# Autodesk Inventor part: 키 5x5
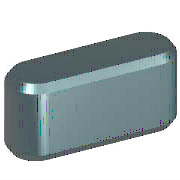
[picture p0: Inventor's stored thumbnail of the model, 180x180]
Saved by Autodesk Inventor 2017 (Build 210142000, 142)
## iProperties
IsCustomPart: 1
Created: 2012-02
Part Number: 키 5x5
Material: 강철, 연강
Description: 키 및 해당 키홈
Document SubType Name: Modeling
Standard: KS B 1311
Designer: mduedu
Standards Organization: KS
Language: ko-KR
Size Designation: 5 x 5 x 18
Categories: <MemberInstance><Categories><Category DisplayName="샤프트 부품" InternalName="7f7aeb1f-a693-4053-b835-cee3144e0d98" Mnemonic="SHFT"><Category DisplayName="키" Interna
Density: 7.85 g/cm^3
Appearance: 노란색
Mass: 3.27059 g
Surface Area: 3.57848 cm^2
Volume: 0.416636 cm^3
Author: mduedu
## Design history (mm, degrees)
workplane "Work Plane1"
workplane "Work Plane2"
sketch "스케치1"
  geometry: L1 (2.5, 2.5)-(15.5, 2.5); L2 (15.5, -2.5)-(2.5, -2.5); L3 (0, 9.4)-(0, -7.4) reference; L4 (-5, 0)-(30, 0) reference; L5 (18, 0)-(18, 7); A1 r 2.5 centre (2.5, 0) between (2.5, 2.5) and (2.5, -2.5); A2 r 2.5 centre (15.5, 0) between (15.5, -2.5) and (15.5, 2.5)
  constraints: 6 end point, 5 point on circle, 4 tangent, 3 point on line, 2 centre point, 1 horizontal, 1 parallel, 1 perpendicular
  dimensions: "d0" = 2.5 radius of A1 (= 0.5 x PB); "d13" = 2.5 radius of A2 (= 0.5 x PB); "d14" = 18 distance between parallel lines of L5 L3 (= NLG)
extrude "본체1" new body sketch "스케치1" taper "d3" = 0 deg; stored distance "d4" = 10
workplane "Work Plane3"
body "Solid1"
chamfer "모따기1" distance "d8" = 0.4 (= PHH); stored, may be unused: second distance "d9" = 0.4 (= PHH), angle "d15" = 45 deg
other parameters: "d1" = -3 (= -PNT), "d2" = 2 (= PH - PNT), "NLG" = 18 [user parameter; used in 3 equation terms], "PB" = 5 [user parameter; used in 2 equation terms], "PNT" = 3 [user parameter; used in 2 equation terms], "PH" = 5 [user parameter; used in 1 equation term], "PHH" = 0.4 [user parameter; used in 2 equation terms], "d10" = 0, "d16" = 0, "d17" = 0, "d18" = 0, "WDMIN" = 12 [user parameter], "PLB2" = 18 (= NLG) [user parameter], "WDMAX" = 17 [user parameter], "PLB1" = 18 (= NLG) [user parameter], "RR" = 0.16 [user parameter], "PUEB" = 2.3 [user parameter]
